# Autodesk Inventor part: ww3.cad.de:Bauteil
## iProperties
Created: 2008-02
Material: Standard
Document SubType Name: Modeling
Designer: Manfred Zirk
Mass: 11.471 g
Surface Area: 81.598 cm^2
Volume: 11.471 cm^3
Density: 1 g/cm^3
Author: Manfred Zirk
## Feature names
1. Rotationswinkel1 [Revolution]
2. Rundung2 [Fillet]
